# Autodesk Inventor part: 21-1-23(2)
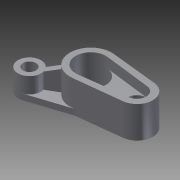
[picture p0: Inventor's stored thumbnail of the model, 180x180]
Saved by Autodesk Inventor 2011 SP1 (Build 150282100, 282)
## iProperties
Created: 2014-01
Part Number: 21-1-23(2)
Document SubType Name: Modeling
Designer: Administrator
Density: 1 g/cm^3
Author: Administrator
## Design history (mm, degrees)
sketch "草图1" dims "d4" = 16
  geometry: L1 (1.548, 14.417)-(33.175, 11.021); L2 (1.623, -14.409)-(33.232, -10.847); L3 (-32.348, -9.639)-(-10.484, 10.017); L4 (-24.522, -23.195)-(2.883, -14.267); A1 r 14.5 centre (0, 0) between (1.548, 14.417) and (1.623, -14.409); A2 r 11 centre (32, 0.083) between (33.232, -10.847) and (33.175, 11.021); 2 further points
  constraints: 8 end point, 5 point on circle, 4 tangent, 2 centre point, 1 coincident, 1 point on line, 4 other
  dimensions: "d0" = 29 diameter of A1; "d1" = 22 diameter of A2; "d2" = 32 distance of A2.centre A1.centre; "d5" = 27 horizontal distance of point (0, 0) point (-27, -15.588)
extrude "拉伸1" new body sketch "草图1" distance "d6" = 22; taper "d7" = 0 deg
sketch "草图2" dims "d9" = 16
  geometry: L1 (-1.623, -14.409)-(-33.232, -10.847) reference; L2 (32.357, -9.646)-(9.709, 10.77); L3 (24.532, -23.198)-(-3.079, -14.245); A1 r 14.5 centre (0, 0) between (-1.623, -14.409) and (-1.548, 14.417) reference; 1 further point
  constraints: 4 end point, 2 tangent, 1 point on circle, 1 point on line, 4 other
  dimensions: "d10" = 27 horizontal distance of A1.centre point (27, -15.588)
extrude "拉伸2" join sketch "草图2" distance "d11" = 15; taper "d12" = 0 deg
hole "Hole1" diameter "d15" = 9; stored, may be unused: countersink angle "d19" = 90 deg, drill point angle "d21" = 118 deg; dims "d13" = 10, "d14" = 10, "d16" = 6, "d17" = 4, "d18" = 2, "d20" = 8
hole "Hole2" diameter "d24" = 21; stored, may be unused: countersink angle "d28" = 90 deg, drill point angle "d30" = 118 deg; dims "d22" = 10, "d23" = 10, "d25" = 6, "d26" = 4, "d27" = 2, "d29" = 8
hole "Hole3" diameter "d33" = 13; stored, may be unused: countersink angle "d37" = 90 deg, drill point angle "d39" = 118 deg; dims "d31" = 10, "d32" = 10, "d34" = 6, "d35" = 4, "d36" = 2, "d38" = 8
sketch "草图3"
  geometry: L1 (1.285, 10.421)-(32.796, 6.535); L2 (1.34, -10.414)-(32.829, -6.363); A1 r 6.5 centre (32, 0.083) between (32.796, 6.535) and (32.829, -6.363) reference; A2 r 10.5 centre (0, 0) between (1.285, 10.421) and (1.34, -10.414) reference
  constraints: 4 end point, 4 point on circle, 4 tangent
extrude "拉伸3" cut sketch "草图3" distance "d40" = 7; taper "d41" = 0 deg
sketch "草图4"
  geometry: L1 (-28.623, 1.18)-(-60.232, 4.741) reference; L2 (-60.175, 26.609)-(-28.548, 30.006) reference; L3 (-2.468, -7.61)-(-30.079, 1.344); L4 (5.357, 5.942)-(-17.291, 26.358); A1 r 8 centre (0, 0) between (-2.468, -7.61) and (5.357, 5.942) reference; A2 r 14.5 centre (-27, 15.588) between (-28.623, 1.18) and (-28.548, 30.006) reference; 1 further point
  constraints: 4 end point, 4 tangent, 3 point on circle, 1 point on line
extrude "拉伸4" join sketch "草图4" distance "d42" = 4; taper "d43" = 0 deg
node "工作平面1"
sketch "草图6"
  geometry: L1 (15, 8)-(15, -8) reference; L2 (22, 39.726)-(22, 16.677) reference; L3 (4, 8)-(15, 8) reference; L4 (4, 16.677)-(22, 16.677) reference; L5 (15, 8)-(18, 16.677); 2 further points
  constraints: 2 end point, 1 point on line
  dimensions: "d46" = 4 distance of L5.end L2.end
feature "加强筋1" sketch "草图6" dims "d47" = 1, "d48" = 4, "d49" = 0
node "实体1"
